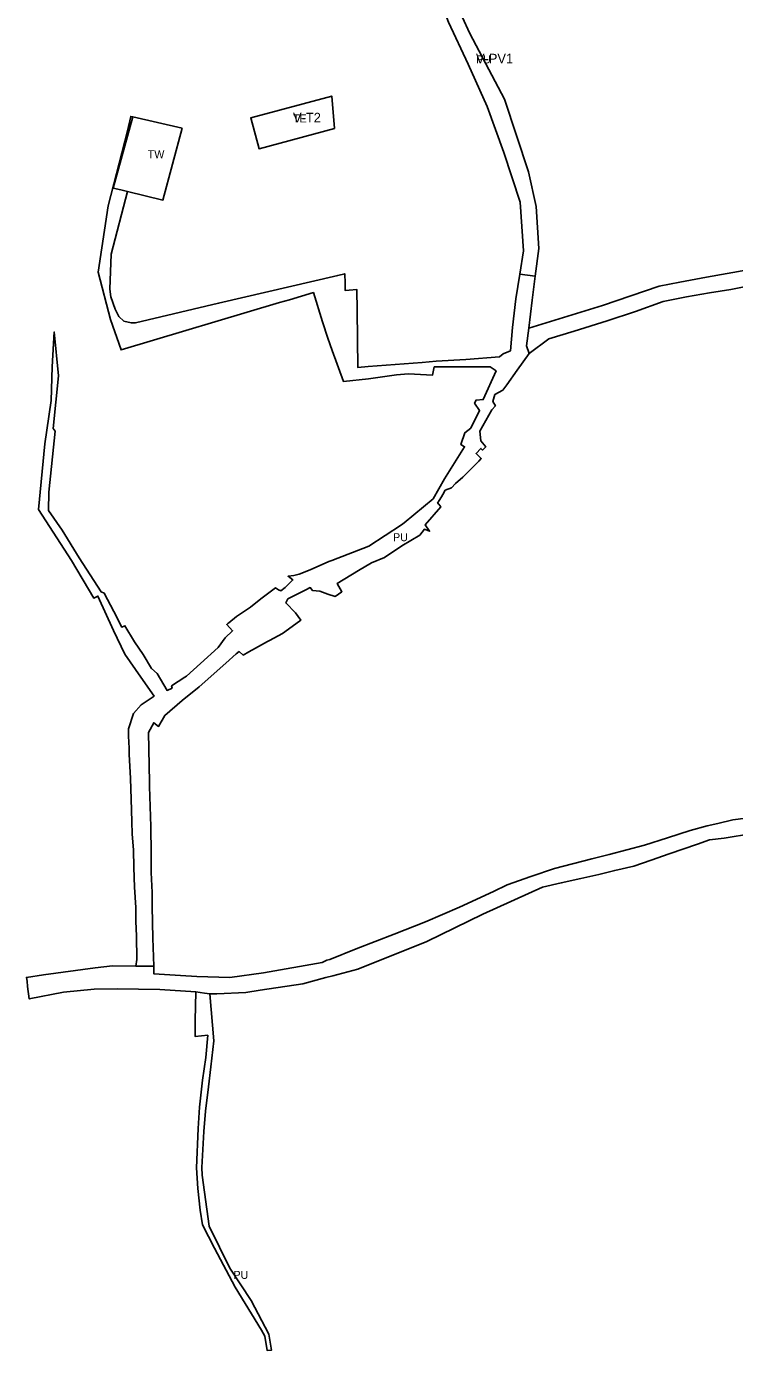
# Model space of a CAD drawing. Extents: x -532083 to -529750, y -1178838 to -1176858.
# Drawn here: x -532083 to -531640, y -1178719 to -1177892 of the extents above; entities that cross this region are included whole.
import ezdxf

# ---------------------------------------------------------------- set-up
doc = ezdxf.new("R2010")
doc.units = 0
for name, color, linetype in [('90320013', 7, 'Continuous'), ('90390013', 7, 'Continuous'), ('90400023', 7, 'Continuous'), ('90450013', 7, 'Continuous'), ('90450023', 7, 'Continuous'), ('ID_navrh', 7, 'Continuous')]:
    doc.layers.add(name, color=color, linetype=linetype)

msp = doc.modelspace()

# ---------------------------------------------------------------- linework, layer by layer
at = {"layer": '90320013'}
msp.add_lwpolyline([(-531629.1453, -1178396.55945), (-531646.7993, -1178399.28445), (-531656.0333, -1178400.50945), (-531663.5023, -1178403.23445), (-531681.2663, -1178409.22045), (-531692.3883, -1178413.10045), (-531703.3483, -1178416.81945), (-531715.2753, -1178419.56745), (-531725.2683, -1178421.99245), (-531736.3893, -1178424.57945), (-531748.6383, -1178427.32845), (-531760.3053, -1178429.91445), (-531797.6843, -1178446.77645), (-531832.6313, -1178463.85945), (-531875.7613, -1178481.16445), (-531891.4143, -1178485.30245), (-531895.6863, -1178486.37445), (-531910.1023, -1178490.30145), (-531936.7993, -1178494.40745), (-531945.6983, -1178495.83645), (-531963.8523, -1178496.72845), (-531968.1243, -1178496.72845), (-531971.5293, -1178496.23845), (-531976.8013, -1178495.47945), (-531999.4463, -1178493.94245), (-532026.0063, -1178493.60045), (-532040.4783, -1178493.77145), (-532059.5473, -1178495.65045), (-532080.9713, -1178499.83145), (-532081.9923, -1178492.14745), (-532082.3333, -1178488.73245), (-532082.6733, -1178486.34145), (-532071.9463, -1178484.85345), (-532039.8533, -1178480.42445), (-532028.8773, -1178479.10845), (-532014.3303, -1178479.26545), (-532003.0803, -1178479.26545), (-532003.0803, -1178484.23045), (-531986.4303, -1178485.13345), (-531976.3063, -1178485.81045), (-531955.6063, -1178486.48745), (-531934.6823, -1178483.55345), (-531898.0073, -1178477.00845), (-531894.9673, -1178475.68145), (-531893.1383, -1178475.25745), (-531876.8213, -1178468.62645), (-531852.9093, -1178459.31445), (-531833.4983, -1178451.69545), (-531812.2103, -1178442.57245), (-531790.9153, -1178432.60345), (-531782.3973, -1178428.61645), (-531767.6143, -1178423.42645), (-531752.9003, -1178418.33745), (-531729.5603, -1178412.22945), (-531718.6523, -1178409.68545), (-531707.7433, -1178406.63145), (-531696.5803, -1178403.83245), (-531682.3733, -1178399.25245), (-531668.1663, -1178394.67145), (-531657.5693, -1178391.60445), (-531650.9173, -1178390.16245), (-531641.3883, -1178387.99745), (-531633.4203, -1178386.90845)], dxfattribs=at)
at = {"layer": '90390013'}
msp.add_lwpolyline([(-531985.4293, -1177955.73145), (-531997.4373, -1178000.70345), (-532019.6403, -1177995.37945), (-532023.6943, -1177994.42645), (-532028.4663, -1177993.30545), (-532016.3003, -1177948.73445)], close=True, dxfattribs=at)
at = {"layer": '90400023'}
msp.add_lwpolyline([(-531890.2323, -1177955.99345), (-531937.3493, -1177968.71045), (-531942.5603, -1177949.40145), (-531892.0483, -1177935.76845)], close=True, dxfattribs=at)
at = {"layer": '90450013'}
for points in [[(-532021.9303, -1178076.45745), (-532017.2153, -1178077.52145), (-532014.6303, -1178077.36945), (-531962.7363, -1178065.22045), (-531888.2813, -1178047.78945), (-531883.8673, -1178046.75645), (-531883.6763, -1178052.70245), (-531883.5303, -1178057.25145), (-531881.1593, -1178057.02345), (-531876.3873, -1178056.56445), (-531876.2103, -1178069.69145), (-531875.7293, -1178105.31945), (-531869.3403, -1178104.69245), (-531835.4643, -1178102.27945), (-531826.8443, -1178101.47545), (-531808.2023, -1178100.26845), (-531787.1773, -1178098.75445), (-531784.9973, -1178096.75045), (-531780.3793, -1178094.84245), (-531779.1413, -1178080.31945), (-531777.0283, -1178062.36345), (-531774.5653, -1178047.08845), (-531764.8393, -1178048.36745), (-531766.8093, -1178063.34245), (-531768.9703, -1178080.71945), (-531770.3563, -1178091.86345), (-531768.7073, -1178096.62645), (-531776.1283, -1178106.96545), (-531782.6543, -1178116.17645), (-531785.1773, -1178119.41045), (-531790.0843, -1178122.22345), (-531791.4863, -1178126.58245), (-531789.8043, -1178129.25445), (-531792.0013, -1178131.77745), (-531799.4213, -1178145.21745), (-531798.8033, -1178151.21445), (-531795.8253, -1178154.86245), (-531797.8343, -1178156.88645), (-531798.8163, -1178155.91145), (-531801.8783, -1178158.99545), (-531798.6033, -1178162.24645), (-531800.1043, -1178163.75845), (-531810.0833, -1178173.81145), (-531814.6973, -1178177.72245), (-531817.2283, -1178180.54245), (-531821.0793, -1178182.07045), (-531822.6673, -1178184.72445), (-531823.4913, -1178186.10245), (-531824.8853, -1178188.43245), (-531825.8743, -1178190.08545), (-531825.2133, -1178190.76345), (-531823.9013, -1178192.31145), (-531833.6303, -1178203.57245), (-531830.9113, -1178207.69145), (-531834.1153, -1178206.36645), (-531837.0083, -1178209.99845), (-531848.1263, -1178216.77845), (-531859.0643, -1178223.97245), (-531867.2543, -1178227.41645), (-531875.2343, -1178232.21945), (-531888.7183, -1178240.33445), (-531885.6753, -1178245.39145), (-531889.8463, -1178248.33345), (-531894.4123, -1178246.97645), (-531899.4863, -1178245.11045), (-531904.0383, -1178244.56245), (-531905.3823, -1178242.82845), (-531908.2633, -1178244.17745), (-531919.4023, -1178249.95645), (-531920.7103, -1178252.41845), (-531914.6013, -1178258.62545), (-531911.3363, -1178263.24945), (-531914.5303, -1178265.54545), (-531922.8593, -1178271.53345), (-531930.8433, -1178275.92345), (-531932.0303, -1178276.53145), (-531939.6183, -1178280.74645), (-531943.7333, -1178283.03245), (-531947.3593, -1178285.04645), (-531949.7983, -1178282.87145), (-531951.7253, -1178284.22345), (-531958.1093, -1178290.12945), (-531974.7633, -1178304.87645), (-531985.4873, -1178313.41945), (-531996.1743, -1178322.74145), (-532000.2013, -1178329.57745), (-532003.1543, -1178327.26245), (-532006.3643, -1178333.28645), (-532005.8403, -1178364.44845), (-532005.8403, -1178367.13645), (-532005.0163, -1178392.15645), (-532004.8563, -1178408.99845), (-532004.7073, -1178420.74945), (-532004.2623, -1178433.24445), (-532004.1143, -1178442.16845), (-532003.7043, -1178461.93145), (-532003.0803, -1178479.26545), (-532014.3303, -1178479.26545), (-532013.7863, -1178475.21845), (-532014.0473, -1178460.31845), (-532014.4423, -1178451.35845), (-532014.4423, -1178442.73445), (-532015.1373, -1178430.02245), (-532015.6953, -1178417.70045), (-532015.8813, -1178406.68645), (-532016.6253, -1178396.79245), (-532016.8123, -1178388.95245), (-532017.3703, -1178374.95045), (-532017.7423, -1178362.06945), (-532018.4873, -1178346.94745), (-532018.6103, -1178343.23645), (-532018.8593, -1178335.74645), (-532018.8593, -1178331.07945), (-532015.8893, -1178321.40045), (-532010.9433, -1178316.03645), (-532002.9223, -1178310.67245), (-532011.3443, -1178298.87245), (-532021.2363, -1178284.39045), (-532028.2883, -1178269.69545), (-532038.0993, -1178248.15845), (-532040.6593, -1178249.44245), (-532054.6243, -1178225.87345), (-532075.1263, -1178194.13345), (-532071.2143, -1178153.06145), (-532069.9873, -1178144.58845), (-532067.2883, -1178125.95045), (-532066.6333, -1178104.95145), (-532065.3253, -1178083.07645), (-532062.5813, -1178110.47545), (-532066.0193, -1178143.52345), (-532064.7313, -1178145.04345), (-532068.6933, -1178183.15145), (-532069.0133, -1178194.63945), (-532060.2853, -1178206.94345), (-532049.6703, -1178224.21645), (-532035.9283, -1178245.58845), (-532034.0933, -1178246.22745), (-532028.0963, -1178257.78345), (-532023.2133, -1178267.49245), (-532021.2433, -1178266.64745), (-532015.1253, -1178276.66045), (-532009.8663, -1178284.73445), (-532004.4993, -1178293.45545), (-532001.0653, -1178296.46945), (-531994.9013, -1178307.05245), (-531991.6923, -1178305.71145), (-531992.0933, -1178304.23645), (-531983.8053, -1178298.73845), (-531982.6743, -1178298.08545), (-531974.0173, -1178290.22545), (-531962.9503, -1178280.23345), (-531958.5963, -1178274.12845), (-531953.9563, -1178269.82745), (-531957.6333, -1178265.86045), (-531956.9253, -1178265.31445), (-531956.2613, -1178264.79145), (-531951.4083, -1178260.97245), (-531942.7343, -1178255.03045), (-531936.3853, -1178249.88145), (-531927.2363, -1178243.00645), (-531925.3043, -1178244.33445), (-531923.8133, -1178244.78145), (-531921.1063, -1178242.70445), (-531916.2563, -1178238.08045), (-531919.2333, -1178235.71045), (-531915.7313, -1178235.20945), (-531912.2803, -1178234.48045), (-531905.4583, -1178231.71445), (-531893.8663, -1178226.52545), (-531892.0013, -1178225.94945), (-531868.8023, -1178216.92845), (-531848.4643, -1178203.70445), (-531846.7873, -1178202.32245), (-531828.6903, -1178187.35445), (-531821.4943, -1178174.82845), (-531809.0063, -1178154.87145), (-531811.3343, -1178153.49145), (-531808.9713, -1178146.12145), (-531805.1573, -1178143.20645), (-531799.7093, -1178132.27545), (-531802.7963, -1178127.72145), (-531801.8883, -1178125.71745), (-531797.3483, -1178125.35245), (-531789.3563, -1178107.49945), (-531792.9893, -1178104.94845), (-531808.9213, -1178104.95345), (-531823.3853, -1178104.95345), (-531827.9273, -1178104.93045), (-531828.9913, -1178110.03245), (-531844.0773, -1178109.35745), (-531851.5263, -1178109.84845), (-531869.1393, -1178112.33245), (-531884.7513, -1178114.05445), (-531891.8283, -1178094.67145), (-531894.5453, -1178087.08045), (-531897.7203, -1178076.91345), (-531903.4683, -1178058.50145), (-531918.3243, -1178063.13945), (-531924.5573, -1178064.66545), (-532023.5883, -1178094.38545), (-532030.2473, -1178075.32345), (-532037.9833, -1178045.77745), (-532031.7353, -1178004.29445), (-532019.5363, -1177957.43845), (-532017.5013, -1177948.46245), (-532016.3003, -1177948.73445), (-532028.4663, -1177993.30545), (-532023.6943, -1177994.42645), (-532019.6403, -1177995.37945), (-532029.8433, -1178034.48045), (-532030.6043, -1178056.38545), (-532029.9963, -1178061.25345), (-532027.2523, -1178069.00345), (-532024.9713, -1178073.41445)], [(-531968.1243, -1178496.72845), (-531965.6323, -1178526.00745), (-531967.5903, -1178542.25345), (-531969.0663, -1178554.81745), (-531970.8583, -1178570.00245), (-531971.8543, -1178582.58945), (-531973.2483, -1178605.16645), (-531972.8503, -1178609.96245), (-531968.5923, -1178641.79245), (-531955.6433, -1178668.07945), (-531942.3853, -1178688.18245), (-531931.2863, -1178709.21245), (-531929.5503, -1178719.17845), (-531932.2803, -1178719.47245), (-531933.8663, -1178710.45645), (-531935.9813, -1178706.74345), (-531952.3733, -1178679.95745), (-531965.1453, -1178655.58545), (-531972.7253, -1178640.98645), (-531974.2423, -1178631.71045), (-531975.6063, -1178618.17645), (-531976.5723, -1178605.33645), (-531975.5243, -1178580.76145), (-531974.6543, -1178567.45245), (-531972.6973, -1178550.65345), (-531970.7393, -1178536.47245), (-531969.4343, -1178522.50845), (-531977.2643, -1178523.38145), (-531977.2643, -1178513.34545), (-531976.8013, -1178495.47945), (-531971.5293, -1178496.23845)]]:
    msp.add_lwpolyline(points, close=True, dxfattribs=at)
at = {"layer": '90450023'}
msp.add_lwpolyline([(-531762.5543, -1178030.99145), (-531764.8393, -1178048.36745), (-531774.5653, -1178047.08845), (-531772.2003, -1178032.42445), (-531774.3943, -1178002.04445), (-531784.4443, -1177970.98845), (-531794.8753, -1177942.31245), (-531806.8203, -1177915.90545), (-531819.0393, -1177889.54245), (-531835.4083, -1177846.99045), (-531841.2853, -1177829.40045), (-531834.6043, -1177825.98245), (-531829.0433, -1177841.54345), (-531810.6313, -1177886.29445), (-531805.7253, -1177896.68445), (-531784.1913, -1177937.69645), (-531769.1993, -1177983.08345), (-531764.3573, -1178004.76845)], close=True, dxfattribs=at)
msp.add_lwpolyline([(-531630.2673, -1178054.12845), (-531642.7123, -1178056.59445), (-531656.0973, -1178058.76345), (-531670.3443, -1178061.24845), (-531685.0033, -1178064.14845), (-531702.3463, -1178070.36145), (-531719.8963, -1178076.16045), (-531740.5423, -1178082.58045), (-531756.4403, -1178087.34345), (-531768.7073, -1178096.62645), (-531770.3563, -1178091.86345), (-531768.9703, -1178080.71945), (-531722.9873, -1178066.64845), (-531687.5603, -1178054.45245), (-531674.5133, -1178052.02145), (-531657.8963, -1178048.92645), (-531632.1983, -1178044.31545)], dxfattribs=at)

# ---------------------------------------------------------------- texts
at = {"layer": '90390013'}
msp.add_text('TW', height=5, rotation=359.99999999, dxfattribs=at).set_placement((-532006.9478, -1177974.63859))
at = {"layer": '90400023'}
msp.add_text('TE', height=5, rotation=0.00000004, dxfattribs=at).set_placement((-531916.18188, -1177952.23945))
at = {"layer": '90450013'}
for rotation, p in [(359.99999996, (-531853.71813, -1178213.86395)), (0.00000005, (-531953.4073, -1178674.72711))]:
    msp.add_text('PU', height=5, rotation=rotation, dxfattribs=at).set_placement(p)
at = {"layer": '90450023'}
msp.add_text('PU', height=5, rotation=359.99999994, dxfattribs=at).set_placement((-531801.9198, -1177915.33559))
at = {"layer": 'ID_navrh'}
for s, rotation, p in [('V-PV1', 0.00000002, (-531801.9198, -1177915.33559)), ('V-T2', 0.00000004, (-531916.18188, -1177952.23945))]:
    msp.add_text(s, height=6, rotation=rotation, dxfattribs=at).set_placement(p)

doc.saveas('drawing.dxf')
